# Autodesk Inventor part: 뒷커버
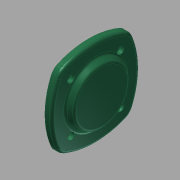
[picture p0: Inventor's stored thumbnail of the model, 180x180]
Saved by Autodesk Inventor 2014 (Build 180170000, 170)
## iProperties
Created: 2015-11
Part Number: 뒷커버
Material: 일반
Document SubType Name: Modeling
Designer: mduedu
Density: 1 g/cm^3
Appearance: 매끄러움 - 짙은 바다 녹색
Mass: 120.055 g
Surface Area: 247.582 cm^2
Volume: 120.055 cm^3
Author: mduedu
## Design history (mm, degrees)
sketch "스케치1"
  geometry: L1 (50, 50)-(-50, 50); L2 (-50, 50)-(-50, -50); L3 (-50, -50)-(50, -50); L4 (50, -50)-(50, 50); L5 (0, 50)-(0, -50); L6 (50, 0)-(-50, 0); A1 r 90 centre (-40, 0) between (40.415, -40.415) and (40.415, 40.415); A2 r 90 centre (40, 0) between (-40.415, 40.415) and (-40.415, -40.415); A3 r 90 centre (0, -40) between (40.415, 40.415) and (-40.415, 40.415); A4 r 90 centre (0, 40) between (-40.415, -40.415) and (40.415, -40.415); 2 further points
  constraints: 12 end point, 8 point on circle, 5 midpoint, 4 centre point, 2 horizontal alignment, 2 parallel, 2 perpendicular, 2 symmetric about line, 2 tangent, 2 vertical alignment, 1 equal radius, 1 horizontal, 2 other
  dimensions: "d0" = 100 distance of L3.end L1.start; "d2" = 90 radius of A1
extrude "돌출1" new body sketch "스케치1" distance "d3" = 8; taper "d4" = 0 deg
sketch "스케치2"
  geometry: C1 r 35 at (0, 0); 1 further point
  constraints: 1 centre point, 1 coincident
  dimensions: "d5" = 70 diameter of C1
extrude "돌출2" join sketch "스케치2" distance "d6" = 7; taper "d7" = -30 deg
sketch "스케치3"
  geometry: L1 (0, 0)-(0, 40); L2 (0, 0)-(-28.284, 28.284); A1 r 40 centre (0, 0) between (0, 40) and (-28.284, 28.284); 2 further points
  constraints: 4 end point, 2 coincident, 2 point on circle, 1 centre point, 1 vertical
  dimensions: "d8" = 80 diameter of A1; "d9" = 45 deg angle of L1 L2
hole "구멍1" sketch "스케치3" at (-28.284, 28.284) diameter "d11" = 4.5; stored, may be unused: countersink angle "d15" = 90 deg, drill point angle "d17" = 118 deg; dims "d12" = 6, "d13" = 8, "d14" = 4.4, "d16" = 8
sketch "스케치4"
  geometry: C1 r 35 at (0, 0); 1 further point
  constraints: 1 centre point, 1 coincident
  dimensions: "d21" = 70 diameter of C1
extrude "돌출3" join sketch "스케치4" distance "d23" = 12; taper "d24" = 0 deg
hole "구멍2" diameter "d27" = 30; stored, may be unused: countersink angle "d31" = 90 deg, drill point angle "d33" = 0 deg; dims "d25" = 10, "d26" = 10, "d28" = 6, "d29" = 40, "d30" = 12, "d32" = 15
fillet "모깎기2" dims "d35" = 15
fillet "모깎기3" dims "d36" = 3
fillet "모깎기4" dims "d37" = 3
fillet "모깎기5" dims "d38" = 0.3
chamfer "모따기1" distance "d39" = 1; stored, may be unused: second distance "d40" = 2, angle "d41" = 45 deg
node "솔리드1"
pattern_circular "원형 패턴1" dims angle "d19" = 360 deg
